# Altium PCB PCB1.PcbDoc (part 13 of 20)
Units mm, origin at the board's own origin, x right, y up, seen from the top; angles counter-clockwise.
Board outline 294.51 x 138.18 mm, 12 copper layers (Top Layer 1 _Signal, L2_GND, L3_Signals, L4_GND, L5_POWER, L6_Signals, L7_GND, L8_Signals, L9_GND, L10_POWER, L11_GND, Bottom Layer_Signals), stack 1.788 mm thick; 1254 components, 836 nets, 5699 pads, 2073 vias.
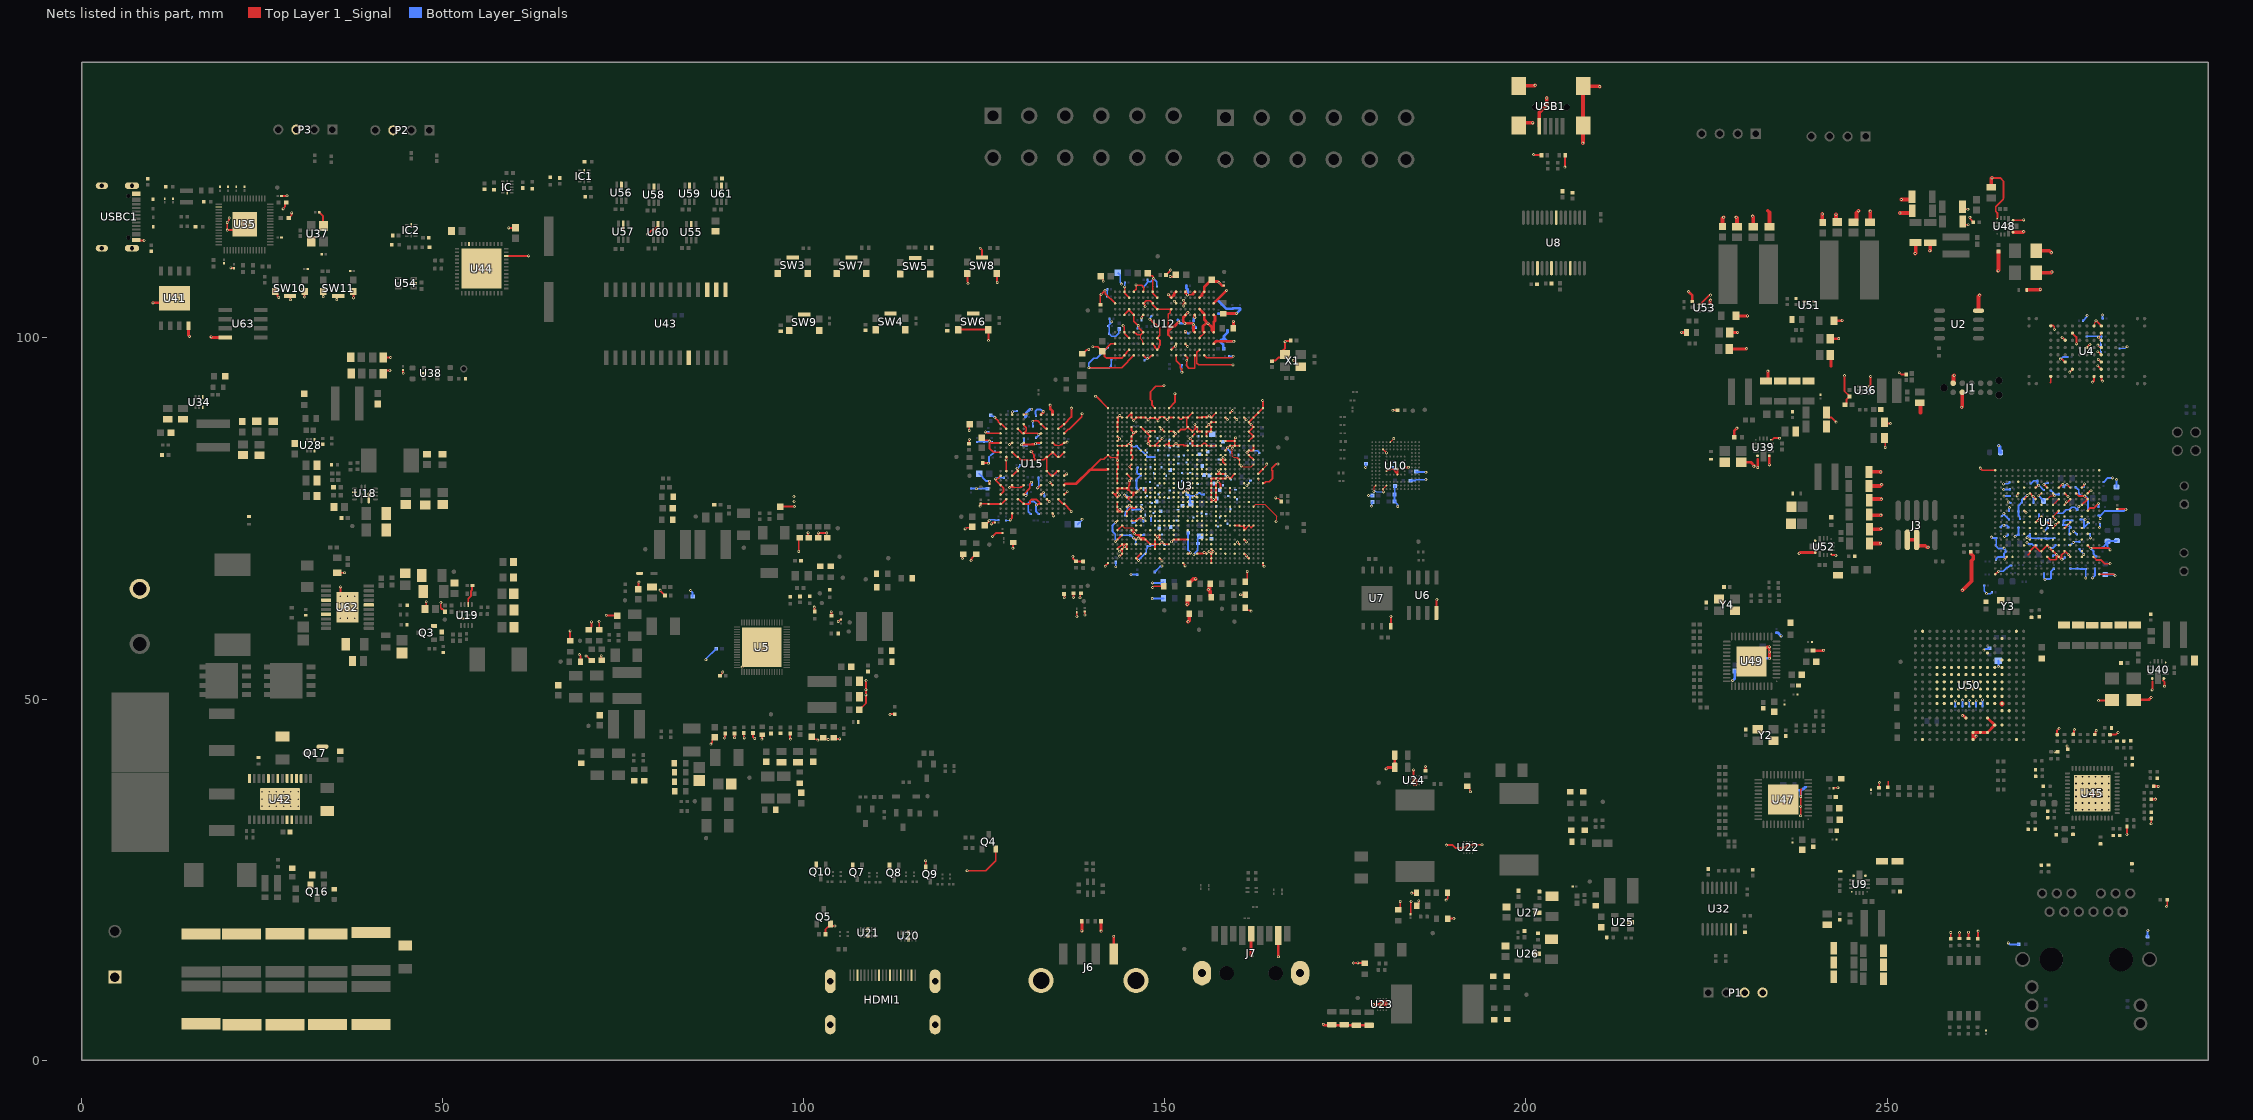
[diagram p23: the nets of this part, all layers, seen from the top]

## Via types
v1: diameter 0.4, hole 0.2, Top Layer 1 _Signal to Bottom Layer_Signals, 2009 vias
v2: diameter 0.508, hole 0.254, Top Layer 1 _Signal to Bottom Layer_Signals, 36 vias
v3: diameter 0.5, hole 0.2, Top Layer 1 _Signal to Bottom Layer_Signals, 12 vias
v4: diameter 1.27, hole 0.711, Top Layer 1 _Signal to Bottom Layer_Signals, 6 vias
v5: diameter 0.3, hole 0.2, Top Layer 1 _Signal to Bottom Layer_Signals, 5 vias
v6: diameter 0.254, hole 0.2, Top Layer 1 _Signal to Bottom Layer_Signals, 3 vias
v7: diameter 0.305, hole 0.2, Top Layer 1 _Signal to Bottom Layer_Signals, 1 vias
v8: diameter 0.254, hole 0.152, Top Layer 1 _Signal to Bottom Layer_Signals, 1 vias

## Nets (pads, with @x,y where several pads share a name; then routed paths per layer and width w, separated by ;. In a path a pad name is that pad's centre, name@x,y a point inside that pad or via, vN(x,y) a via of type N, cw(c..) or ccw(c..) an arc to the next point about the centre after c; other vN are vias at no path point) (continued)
GND: (continued)
  Top Layer 1 _Signal w0.254: USBC1.B1_A12@7.558,113.555 7.6,113.513 v1(8.645,113.513) ; v1(20.44,116.607) 20.413,116.579 20.413,116.289 20.161,116.038 v1(20.161,115.998) 20.161,115.51 20.168,115.504 v1(20.168,114.923) 21.764,114.923 U35.61@22.569,115.727 ; v1(20.675,109.706) 20.692,109.69 21.105,109.69 21.109,109.685 C565.1@21.109,109.673 ; SW10.2@26.807,106.414 27.13,106.091 27.13,105.796 27.301,105.624 27.301,105.619 v1(27.304,105.616) ; C574.1@27.682,119.646 28.404,119.646 v1(28.444,119.686) ; v1(27.903,117.875) 27.903,117.915 28.185,118.197 28.185,118.634 28.308,118.757 C453.1@28.358,118.757 ; C451.1@28.692,116.61 28.742,116.61 28.865,116.733 28.865,116.783 29.068,116.986 29.068,117.279 v1(29.096,117.307) ; SW10.5@28.857,105.789 28.902,105.744 v1(28.902,105.285) ; v1(30.886,105.668) 30.886,106.393 SW10.1@30.907,106.414 ; C560.2@32.89,117.388 32.91,117.388 33.408,116.891 33.408,115.615 U37.2@33.497,115.526 ; v1(33.458,105.711) 33.458,106.385 SW11.2@33.493,106.419 ; v1(35.335,105.297) 35.335,105.646 35.483,105.794 SW11.5@35.543,105.794 ; R302.1@35.411,67.487 35.415,67.482 v1(36.42,67.482) ; v3(35.818,64.211) 35.859,64.253 v1(35.859,65.517) ; SW11.1@37.593,106.419 37.652,106.36 v1(37.652,105.543) ; C483.2@41.776,95.03 41.776,95.109 42.176,95.51 v1(42.679,95.51) ; C484.2@41.776,97.293 v1(42.783,97.293) v1@42.825,97.335 ; C194.1@44.492,95.549 44.492,95.161 v1(44.541,95.113) ; C198.1@47.565,62.464 47.728,62.626 v1(47.728,63.461) ; v1(49.746,63.343) 49.731,63.329 49.731,62.607 49.897,62.442 49.976,62.442 50.29,62.128 R86.1@50.29,62.103 ; U19.10@53.538,63.083 53.538,63.889 53.937,64.288 53.937,64.985 54.074,65.122 54.074,65.668 R88.1@54.133,65.728 ; U44.46@58.789,111.359 58.791,111.357 61.899,111.357 v1(61.903,111.352) ; v1(59.153,115.242) 60.04,115.242 C591.2@60.074,115.276 ; v1(67.638,59.431) C181.2@67.639,58.084 C181.2@67.639,58.084 ; v1(68.924,56.152) 68.924,56.112 69.089,55.947 C180.2@69.089,55.175 ; v1(69.843,55.96) 69.965,55.96 70.588,55.337 C66.2@70.663,55.337 ; C65.2@70.255,59.598 70.33,59.598 70.578,59.846 70.578,59.921 70.609,59.952 v1(70.609,60.675) ; v1(71.655,60.707) 71.676,60.686 C61.2@71.676,59.614 ; v1(71.953,55.992) 71.953,55.433 C67.2@72.025,55.361 ; v1(72.654,61.603) 72.693,61.603 72.745,61.55 C442.2@74.177,61.55 ; C59.2@77.102,65.213 77.102,66.071 77.187,66.155 v1(77.187,66.195) ; v1(80.1,65.077) 80.1,65.019 C314.1@80.773,64.346 ; v1(87.138,43.767) 87.138,43.807 87.317,43.986 87.317,44.382 C444.2@87.64,44.705 ; C558.1@88.386,53.208 88.716,53.537 88.716,53.683 v1(88.775,53.741) ; v1(89.045,44.601) 89.073,44.629 89.073,45.162 C557.1@89.126,45.216 ; C556.1@90.412,45.232 90.413,45.232 v1(90.414,44.634) v1(90.414,44.634) ; v1(91.458,54.429) U5.69@94.199,57.17 ; C553.2@91.693,45.282 91.693,44.691 v1(91.758,44.626) ; C555.1@92.963,45.284 92.963,44.758 93.18,44.541 v1(93.215,44.541) ; v1(94.193,44.457) 94.21,44.474 94.21,45.025 R20.1@94.227,45.042 ; C446.2@96.775,76.616 96.806,76.647 v1(98.704,76.647) ; R37.1@98.108,45.21 98.108,44.559 98.177,44.489 v1(98.177,44.45) ; v1(99.304,70.432) 99.304,72.198 C164.2@99.431,72.324 ; v1(100.594,73.03) 100.594,72.415 C165.2@100.706,72.304 ; C72.2@101.112,44.752 101.435,44.429 101.794,44.429 101.914,44.309 v1(101.953,44.309) ; v1(101.451,62.723) 101.478,62.696 101.478,62.142 C171.2@101.505,62.115 ; C166.2@101.976,72.304 102.017,72.345 v1(102.017,72.993) 102.021,72.989 103.185,72.989 v1(103.189,72.985) ; C71.2@102.725,44.648 102.949,44.423 103.361,44.423 v1(103.389,44.395) ; R105.1@102.999,17.418 102.999,18.085 103.383,18.47 103.504,18.47 103.702,18.668 Q5.2@103.702,18.764 ; Q5.2@103.702,18.843 Q5.2@103.702,18.764 ; v1(103.802,62.089) 103.821,62.071 103.821,61.522 C172.2@103.84,61.504 ; C70.2@104.121,44.638 104.288,44.471 v1(104.987,44.471) ; v1(104.319,18.566) 103.9,18.566 Q5.2@103.702,18.764 ; v1(104.768,60.747) 104.808,60.747 105.047,60.986 105.153,60.986 C176.1@105.166,60.999 ; C49.2@107.701,48.494 108.614,49.407 108.614,50.553 v1(108.602,50.566) v1(108.602,51.291) 108.602,51.906 108.627,51.932 v1(108.627,52.548) ; v1(111.941,47.855) 111.981,47.855 112.034,47.908 C467.2@112.586,47.908 ; v1(116.864,27.606) 116.864,27.563 116.884,27.544 Q9.2@116.884,26.607 ; SW6.3@121.419,101.145 SW6.4@125.519,101.145 125.58,101.084 v1(125.58,99.636) ; v1(121.963,69.435) 121.963,69.971 C235.2@122.062,70.07 ; v1(122.344,73.554) 122.383,73.554 122.554,73.724 123.217,73.724 C431.2@123.357,73.864 ; v1(122.614,26.214) 125.21,26.214 126.574,27.577 Q4.2@126.574,29.214 ; SW8.3@122.643,108.916 122.694,108.865 122.694,107.783 122.713,107.764 122.713,107.542 v1(122.741,107.514) ; v1(123.181,69.166) 123.209,69.194 123.209,69.419 123.832,70.042 C234.2@123.907,70.042 ; v1(124.423,76.701) 124.423,76.74 124.478,76.795 124.478,77.051 124.491,77.064 C417.2@124.501,77.064 124.511,77.064 124.54,77.035 C420.2@125.571,77.035 125.581,77.035 125.615,77 126.877,77 126.879,77.002 127.232,77.002 U15.C12@127.25,77.021 127.268,77.039 127.418,77.039 U15.D11@128.05,77.671 ; v1(124.435,112.422) 124.693,112.164 SW8.5@124.693,111.141 ; C414.2@124.646,86.165 124.609,86.129 124.9,85.838 125.54,85.838 125.672,85.706 v1(125.711,85.706) ; C415.2@124.772,82.679 124.791,82.66 125.538,82.66 v1(125.557,82.641) ; C432.2@125.089,74.043 125.657,74.611 v1(125.657,74.692) ; C395.2@125.724,79.78 125.727,79.783 125.727,80.148 v1(125.73,80.151) ; v1(125.97,74.251) 126.01,74.251 126.2,74.441 126.433,74.441 126.446,74.454 C410.2@126.446,74.464 ; v1(126.154,72.525) 126.154,72.531 126.623,73 C401.2@127.508,73 ; SW8.4@126.743,108.916 126.743,107.73 v1(126.783,107.69) ; U15.E12@127.25,78.321 127.25,78.335 127.636,78.721 127.636,79.261 127.276,79.621 U15.G12@127.25,79.621 126.602,80.269 126.602,80.446 v1(126.574,80.474) 126.602,80.502 126.831,80.502 U15.J12@127.25,80.921 ; U15.P12@127.25,84.171 126.322,84.171 126.107,84.386 126.01,84.386 125.722,84.674 125.722,85.695 v1(125.711,85.706) ; U15.T12@127.25,85.471 125.986,85.471 125.751,85.706 v1(125.711,85.706) ; U15.K11@128.05,81.571 128.035,81.586 128.035,83.094 v1(128.02,83.109) 128.041,83.13 128.041,83.206 128.06,83.225 128.06,83.51 U15.N11@128.05,83.521 ; v1(128.488,85.246) 128.6,85.246 128.824,85.471 U15.T10@128.85,85.471 ; v1(128.491,79.281) v1@128.501,79.281 ; v1(128.592,74.811) 128.85,75.069 U15.A10@128.85,75.721 ; U15.G10@128.85,79.621 128.84,79.621 v1@128.501,79.281 ; U15.J10@128.85,80.921 129.482,81.552 129.632,81.552 U15.K9@129.65,81.571 129.632,81.589 129.632,81.833 v1(129.535,81.93) ; U15.P10@128.85,84.171 129.482,83.539 129.632,83.539 U15.N9@129.65,83.521 129.665,83.521 130.05,83.135 132.151,83.135 ; v1(128.963,70.876) 128.963,71.647 C412.2@128.994,71.678 ; 129.091,79.3 129.019,79.372 128.622,79.372 128.531,79.281 v1@128.501,79.281 ; U15.D9@129.65,77.671 129.668,77.652 129.792,77.652 130.424,77.021 U15.C8@130.45,77.021 130.468,77.002 130.536,77.002 130.554,76.985 131.19,76.985 131.339,77.134 131.339,77.465 131.488,77.614 132.257,77.614 U15.C5@132.85,77.021 132.832,77.002 132.401,77.002 132.268,76.869 v1(132.228,76.869) ; 129.947,79.304 129.966,79.304 130.003,79.341 130.144,79.341 130.424,79.621 U15.G8@130.45,79.621 ; U15.T8@130.45,85.471 130.45,85.445 v1@130.227,85.222 ; v1(130.752,78.181) 130.724,78.209 130.588,78.209 130.476,78.321 U15.E8@130.45,78.321 131.301,79.171 131.301,79.762 131.522,79.984 v1(131.522,80.023) ; 131.577,85.354 132.085,85.354 v1(132.09,85.35) ; v1@131.653,84.273 131.517,84.273 v1(131.489,84.245) 131.489,84.206 131.876,83.819 131.876,83.409 132.151,83.135 ; v1(131.711,88.466) 131.75,88.466 131.82,88.536 132.384,88.536 U15.Y5@132.85,88.071 132.876,88.071 133.508,87.439 133.632,87.439 U15.W4@133.65,87.421 ; v1(132.381,79.242) 132.446,79.242 132.824,79.621 U15.G5@132.85,79.621 132.842,79.629 U15.G5@132.842,79.651 ; v1(132.546,86.667) 132.586,86.667 132.659,86.74 132.671,86.74 132.683,86.752 132.832,86.752 U15.V5@132.85,86.771 ; U15.E5@132.85,78.321 132.876,78.321 v1(133.17,78.615) ; U15.T5@132.85,85.471 132.25,85.471 132.129,85.35 v1(132.09,85.35) ; U15.D4@133.65,77.671 133.976,77.344 v1(133.991,77.344) ; v1(134.083,79.995) 134.153,79.925 134.153,79.918 U15.G3@134.45,79.621 ; U15.A3@134.45,75.721 134.468,75.702 134.468,75.554 134.544,75.478 134.544,75.381 v1(134.572,75.353) ; U15.T3@134.45,85.471 134.476,85.471 134.8,85.146 135.029,85.146 ; U15.D2@135.25,77.671 135.882,77.039 136.032,77.039 U15.C1@136.05,77.021 136.542,76.528 136.542,76.461 v1(137.03,75.973) ; U15.K2@135.25,81.571 135.232,81.552 135.082,81.552 U15.J3@134.45,80.921 134.432,80.939 134.282,80.939 U15.K4@133.65,81.571 U15.N4@133.65,83.521 ; U15.W2@135.25,87.421 135.276,87.421 135.548,87.693 135.646,87.693 136.024,88.071 U15.Y1@136.05,88.071 137.049,89.07 v1(137.049,90.275) ; C311.2@136.036,64.541 136.086,64.491 136.086,64.033 v1(136.07,64.018) ; U15.E1@136.05,78.321 136.076,78.321 136.453,78.698 v1(136.482,78.698) ; U15.J1@136.05,80.921 136.076,80.921 136.333,81.178 v1(136.413,81.178) ; U15.P1@136.05,84.171 135.418,83.539 135.268,83.539 U15.N2@135.25,83.521 135.232,83.539 135.082,83.539 U15.P3@134.45,84.171 133.818,83.539 133.668,83.539 U15.N4@133.65,83.521 ; U15.V1@136.05,86.771 136.634,87.355 136.738,87.355 138.489,89.106 138.489,89.457 v1(138.538,89.506) ; v1(137.26,69.729) 137.26,69.484 137.675,69.069 C283.1@137.7,69.069 137.711,69.058 138.666,69.058 C289.1@138.677,69.047 ; v1(137.323,64.065) 137.34,64.082 137.34,64.652 C304.1@137.356,64.669 ; v1(138.249,64.018) 138.277,64.045 138.277,64.568 C309.1@138.366,64.657 ; C305.1@138.908,62.103 138.916,62.095 138.916,61.644 v1(138.924,61.636) ; 139.492,81.597 139.653,81.758 141.105,83.209 141.561,83.209 U3.L1@142.129,83.778 ; v1(140.401,91.928) 140.48,91.928 U3.A1@142.129,90.278 ; C340.2@141.306,98.16 141.629,97.837 141.629,97.491 141.917,97.203 144.004,97.203 144.39,97.589 U12.C1@144.404,97.589 144.404,97.615 144.677,97.887 144.677,97.985 145.054,98.363 U12.D2@145.054,98.389 ; U3.L1@142.111,83.778 U3.L1@142.129,83.778 ; 142.58,83.453 142.472,83.453 142.147,83.778 U3.L1@142.129,83.778 ; U3.W2@142.779,78.578 142.797,78.578 143.035,78.34 143.209,78.34 ; v1(143.14,71.82) 143.14,71.823 143.221,71.904 143.237,71.904 143.411,72.078 U3.AJ3@143.429,72.078 U3.AH4@144.079,72.728 ; v1(143.152,74.424) 143.164,74.424 143.418,74.678 U3.AE3@143.429,74.678 ; U3.AG3@143.429,73.378 U3.AF4@144.079,74.028 ; U3.AA3@143.429,77.278 143.417,77.265 143.417,77.196 143.409,77.188 143.409,76.016 143.429,75.996 U3.AC3@143.429,75.978 U3.AC3@143.446,75.978 ; U3.Y3@143.429,77.928 U3.Y3@143.429,77.946 ; U3.U3@143.429,79.878 143.417,79.891 143.417,80.116 143.404,80.129 143.404,81.134 143.429,81.16 U3.R3@143.429,81.178 143.429,81.196 143.329,81.297 143.329,81.709 143.429,81.81 U3.P3@143.429,81.828 143.429,81.846 143.502,81.919 143.502,82.387 143.429,82.46 U3.N3@143.429,82.478 143.436,82.485 v1(143.436,83.048) 143.429,83.055 143.429,83.122 U3.M3@143.429,83.128 ; U3.K3@143.429,84.428 143.429,84.41 143.534,84.305 143.534,83.9 143.429,83.796 U3.L3@143.429,83.778 U3.M3@143.429,83.128 ; U3.J3@143.429,85.078 U3.J4@144.079,85.078 U3.J5@144.729,85.078 144.729,85.096 144.985,85.351 145.156,85.351 v1(145.184,85.379) ; U3.H3@143.429,85.728 143.429,85.746 U3.H3@143.526,85.843 ; U3.G3@143.429,86.378 143.429,86.36 143.721,86.068 v1(143.721,86.04) ; U3.F3@143.429,87.028 143.429,87.046 143.472,87.088 143.472,87.618 143.429,87.66 U3.E3@143.429,87.678 U3.D3@143.429,88.328 143.429,88.346 143.515,88.432 143.515,88.874 143.429,88.96 U3.C3@143.429,88.978 143.447,88.978 143.728,89.259 v1(143.757,89.259) 143.781,89.259 144.061,88.978 U3.C4@144.079,88.978 ; U3.M3@143.436,83.115 143.436,83.121 U3.M3@143.429,83.128 ; U3.H3@143.535,85.834 v1@143.721,86.02 ; v1(143.694,78.274) 143.694,78.21 U3.Y3@143.429,77.946 ; v1(143.763,76.278) 143.746,76.278 U3.AC3@143.446,75.978 ; U3.AC4@144.079,75.978 U3.AC3@143.446,75.978 ; v1(144.398,78.237) 144.42,78.215 144.425,78.215 144.711,77.928 U3.Y5@144.729,77.928 ; U3.AD5@144.729,75.328 U3.AC5@144.729,75.978 144.747,75.978 144.981,76.212 145.066,76.212 145.066,76.296 145.379,76.61 U3.AB6@145.379,76.628 145.397,76.628 145.579,76.446 145.83,76.446 146.011,76.628 U3.AB7@146.029,76.628 ; U3.V5@144.729,79.228 144.711,79.228 U3.V5@144.654,79.17 ; U3.R5@144.729,81.178 U3.T6@145.379,80.528 145.361,80.528 145.092,80.259 v1(145.092,80.22) 145.1,80.212 145.1,79.644 145.009,79.553 145.009,79.074 ; U3.C5@144.729,88.978 U3.B6@145.379,89.628 U3.C6@145.379,88.978 145.379,88.96 145.634,88.706 145.634,88.604 v1(145.662,88.576) 145.662,88.593 146.029,88.961 U3.C7@146.029,88.978 U3.C8@146.679,88.978 U3.C9@147.329,88.978 147.347,88.978 147.666,88.659 v1(147.684,88.659) 147.734,88.709 147.734,88.714 147.979,88.96 U3.C10@147.979,88.978 147.997,88.978 148.047,88.928 148.562,88.928 148.611,88.978 U3.C11@148.629,88.978 148.629,88.96 148.66,88.93 148.66,88.917 v1(149.065,88.511) 149.093,88.539 149.093,88.774 149.279,88.96 U3.C12@149.279,88.978 149.297,88.978 149.395,89.076 149.814,89.076 149.911,88.978 U3.C13@149.929,88.978 149.947,88.978 150.198,88.727 v1(150.385,88.727) 150.405,88.747 150.405,88.786 150.579,88.96 U3.C14@150.579,88.978 U3.C15@151.229,88.978 ; U3.AG6@145.379,73.378 145.392,73.365 145.392,73.296 v1(145.789,72.899) 145.829,72.899 145.999,72.728 U3.AH8@146.679,72.728 146.367,72.416 146.367,72.309 v1(146.339,72.281) 147.109,72.281 U3.AJ9@147.311,72.078 ; U3.AA6@145.379,77.278 U3.Y5@144.729,77.928 ; U3.P6@145.379,81.828 145.379,81.846 145.121,82.104 v6(145.121,82.211) 145.379,82.469 U3.N6@145.379,82.478 ; U3.M6@145.379,83.128 145.379,83.146 145.509,83.275 145.509,83.63 145.379,83.76 U3.L6@145.379,83.778 145.379,83.796 145.294,83.881 145.294,84.325 145.379,84.41 U3.K6@145.379,84.428 U3.J6@145.379,85.078 145.379,85.096 145.329,85.147 145.329,85.659 145.379,85.71 U3.H6@145.379,85.728 U3.G6@145.379,86.378 145.379,86.396 145.635,86.651 145.635,86.843 v1(145.663,86.871) ; U3.E6@145.379,87.678 145.392,87.665 145.392,87.182 145.663,86.911 v1(145.663,86.871) ; v1(145.681,72.312) 145.729,72.264 145.826,72.264 146.011,72.078 U3.AJ7@146.029,72.078 ; 145.682,78.268 145.682,78.258 ; U3.F7@146.029,87.028 146.029,87.024 145.905,86.899 145.691,86.899 v1(145.663,86.871) ; v1(146.349,69.182) 146.337,69.182 146.041,69.478 U3.AN7@146.029,69.478 U3.AM8@146.679,70.128 ; U3.AJ8@146.679,72.078 U3.AJ9@147.311,72.078 ; U3.AB8@146.679,76.628 146.679,76.61 146.865,76.424 146.865,76.322 v1(146.893,76.294) ; U3.V8@146.679,79.228 146.679,79.21 146.649,79.18 146.649,79.157 v1(146.3,78.808) 146.259,78.808 U3.W7@146.029,78.578 U3.W6@145.379,78.578 ; U3.E8@146.679,87.678 U3.F9@147.329,87.028 U3.G10@147.979,86.378 147.979,86.36 147.7,86.081 v1@147.7,85.431 ; U3.W9@147.329,78.578 U3.V9@147.329,79.228 ; v1(147.721,87.048) 147.726,87.053 147.936,87.053 147.961,87.028 U3.F10@147.979,87.028 147.997,87.028 148.106,87.137 148.503,87.137 148.611,87.028 U3.F11@148.629,87.028 ; U3.H10@147.979,85.728 147.979,85.71 v1@147.7,85.431 ; U12.J3@148.304,99.189 148.304,99.163 148.622,98.846 148.622,98.722 U12.K2@148.954,98.389 148.954,98.415 149.176,98.636 149.176,98.865 149.34,99.029 149.34,99.588 148.954,99.974 U12.K4@148.954,99.989 ; v1(148.313,65.443) 148.353,65.443 148.532,65.622 C18.2@149.827,65.622 ; U3.AL11@148.629,70.778 U3.AK11@148.629,71.428 ; U3.AJ11@148.629,72.078 U3.AK11@148.629,71.428 ; U3.AH11@148.629,72.728 148.647,72.728 148.888,72.487 148.968,72.487 v1(148.996,72.459) 149.003,72.459 149.272,72.728 U3.AH12@149.279,72.728 U3.AJ12@149.279,72.078 ; U3.A11@148.629,90.278 148.227,90.681 148.227,91.218 148.008,91.437 148.008,92.558 148.761,93.312 149.733,93.312 149.839,93.418 v1(149.879,93.418) ; U3.AN12@149.279,69.478 149.279,69.467 149.604,69.142 v1(149.604,69.13) ; U3.J12@149.279,85.078 U3.J11@148.629,85.078 ; v1(149.622,86.051) 149.297,85.728 U3.H12@149.279,85.728 U3.J11@148.629,85.078 ; U3.J13@149.929,85.078 149.947,85.078 150.158,85.289 150.35,85.289 150.561,85.078 U3.J14@150.579,85.078 ; 150.455,100.438 U12.N4@150.904,99.989 ; U3.AK14@150.579,71.428 U3.AK13@149.929,71.428 149.911,71.428 149.623,71.716 v1(149.577,71.716) 149.572,71.716 149.284,71.428 U3.AK12@149.279,71.428 U3.AK11@148.629,71.428 ; U3.H14@150.579,85.728 U3.J14@150.579,85.078 ; U3.A14@150.579,90.278 151.398,91.097 v1(151.398,92.275) ; v1(150.92,71.771) 150.929,71.781 150.932,71.781 U3.AJ15@151.229,72.078 U3.AJ16@151.879,72.078 U3.AJ18@153.179,72.078 ; U3.G15@151.229,86.378 151.229,86.396 151.464,86.631 151.464,86.726 v1(151.492,86.754) ; v1@151.542,85.411 151.546,85.411 U3.J16@151.879,85.078 151.897,85.078 152.022,85.202 152.529,85.202 152.641,85.091 153.167,85.091 U3.J18@153.179,85.078 ; v1(151.541,85.412) 151.541,85.401 151.229,85.089 U3.J15@151.229,85.078 U3.J14@150.579,85.078 ; U3.F16@151.879,87.028 151.897,87.028 152.175,87.306 152.79,87.306 U3.E18@153.179,87.696 ; U3.C16@151.879,88.978 151.897,88.978 152.132,88.743 152.277,88.743 152.511,88.978 U3.C17@152.529,88.978 U3.C18@153.179,88.978 ; U3.W17@152.529,78.578 152.547,78.578 152.78,78.811 152.854,78.811 v1(152.882,78.839) ; U3.AM18@153.179,70.128 153.192,70.141 153.429,70.141 153.53,70.242 v1(153.57,70.242) ; U3.V18@153.179,79.228 153.179,79.21 153.433,78.956 153.433,78.92 ; v1(153.502,86.06) 153.502,86.058 153.829,85.73 U3.H19@153.829,85.728 U3.J19@153.829,85.078 U3.J20@154.479,85.078 U3.J21@155.129,85.078 155.142,85.091 155.142,85.173 155.382,85.413 155.592,85.413 155.767,85.239 155.767,85.091 U3.J22@155.779,85.078 U3.J23@156.429,85.078 U3.J24@157.079,85.078 ; U3.F19@153.811,87.028 153.778,87.061 153.179,87.66 U3.E18@153.179,87.678 U3.E18@153.179,87.696 ; U3.G19@153.829,86.378 153.829,86.396 154.097,86.663 154.097,86.669 154.146,86.719 ; U3.F19@153.829,87.028 153.829,87.046 154.2,87.417 154.2,87.935 154.152,87.983 v1(154.152,88.023) ; U3.B19@153.829,89.628 U3.C18@153.179,88.978 ; v1(154.247,78.134) 154.26,78.134 154.466,77.928 U3.Y20@154.479,77.928 ; U3.AM20@154.479,70.128 155.239,70.128 155.398,70.287 v1(155.437,70.287) 155.603,70.287 155.761,70.128 U3.AM22@155.779,70.128 ; U3.E20@154.479,87.678 U3.F20@154.479,87.028 U3.F21@155.129,87.028 ; U3.C20@154.479,88.978 U3.C21@155.129,88.978 155.142,88.991 155.235,88.991 155.273,89.028 155.711,89.028 155.761,88.978 U3.C22@155.779,88.978 155.797,88.978 155.989,89.17 156.12,89.17 v1(156.148,89.198) 156.21,89.198 U3.C23@156.429,88.978 U3.B24@157.079,89.628 ; U12.W4@154.804,99.989 154.804,100.015 154.852,100.063 154.852,100.098 155.436,100.681 155.436,100.771 U12.Y5@155.454,100.789 ; U3.G22@155.779,86.378 U3.F22@155.779,87.028 U3.F23@156.429,87.028 156.417,87.041 156.417,87.132 156.368,87.181 156.368,87.599 156.429,87.66 U3.E23@156.429,87.678 156.429,87.696 156.127,87.998 v1@156.088,87.998 ; U3.E22@155.779,87.678 155.779,87.69 156.076,87.986 v1(156.076,87.998) v1@156.088,87.998 ; v1(156.123,70.441) 156.123,70.438 156.429,70.131 U3.AM23@156.429,70.128 ; U3.AL23@156.429,70.778 156.429,70.76 156.659,70.531 156.659,70.447 v1(156.687,70.419) ; U3.AA23@156.429,77.278 U3.AA23@156.429,77.296 ; U3.D23@156.474,88.409 156.429,88.364 U3.D23@156.429,88.328 ; U3.U24@157.079,79.878 U3.V24@157.079,79.228 U3.W24@157.079,78.578 U3.Y24@157.079,77.928 U3.AA24@157.079,77.278 157.077,77.278 156.73,77.625 v1(156.728,77.625) 156.63,77.527 156.63,77.496 U3.AA23@156.429,77.296 ; U3.R24@157.079,81.178 U3.R25@157.729,81.178 ; U3.D24@157.079,88.328 157.072,88.321 156.436,88.321 U3.D23@156.429,88.328 ; v1(157.377,80.115) 157.377,80.076 157.717,79.737 157.717,79.241 U3.V25@157.729,79.228 ; v1(157.454,81.59) 157.454,81.538 157.479,81.513 157.479,81.446 157.729,81.196 U3.R25@157.729,81.178 ; v1(158.068,83.422) 158.04,83.394 158.04,83.062 158.023,83.045 158.023,82.834 U3.N26@158.379,82.478 ; U3.R26@158.379,81.178 U3.R25@157.729,81.178 ; U3.K26@158.379,84.428 158.379,84.446 158.698,84.764 v1(158.698,84.801) 158.734,84.801 159.011,85.078 U3.J27@159.029,85.078 U3.J28@159.679,85.078 ; U3.H26@158.379,85.728 U3.H28@159.679,85.728 ; U3.C26@158.379,88.978 v1(158.66,88.698) ; U3.B27@159.029,89.628 159.047,89.628 159.372,89.953 v1(159.377,89.953) ; U3.T27@159.042,80.515 U3.T27@159.029,80.528 ; U3.AF28@159.679,74.028 U3.AF29@160.329,74.028 160.347,74.028 160.45,73.925 160.858,73.925 160.961,74.028 U3.AF30@160.979,74.028 U3.AG30@160.979,73.378 U3.AF31@161.629,74.028 161.647,74.028 161.925,73.75 161.984,73.75 162.261,74.028 U3.AF32@162.279,74.028 ; U3.R28@159.679,81.178 U3.T27@159.029,80.528 ; U3.C28@159.679,88.978 159.697,88.978 159.958,88.717 v1(159.958,88.699) ; v1(159.788,86.175) 159.679,86.067 U3.H28@159.679,85.728 ; 160.04,83.399 160.311,83.128 U3.M29@160.329,83.128 ; v1(160.055,71.716) 160.055,71.709 160.329,71.435 U3.AK29@160.329,71.428 ; U3.J29@160.329,85.078 U3.J28@159.679,85.078 ; U3.AM30@160.979,70.128 v1(161.291,69.817) U3.AN31@161.629,69.478 ; U3.AJ30@160.979,72.078 160.979,72.06 161.26,71.78 161.26,71.775 v1(161.285,71.75) ; U3.C30@160.979,88.978 160.979,88.96 161.244,88.695 161.244,88.687 v1(161.254,88.676) ; v1(161.372,84.113) 161.412,84.113 161.726,84.428 U3.K32@162.279,84.428 U3.J32@162.279,85.078 ; U3.L31@161.629,83.778 U3.M32@162.279,83.128 ; U3.H31@161.629,85.728 U3.G32@162.279,86.378 162.279,86.384 162.162,86.502 162.155,86.502 U3.F31@161.629,87.028 U3.E32@162.279,87.678 162.268,87.678 161.951,87.995 v1(161.94,87.995) 161.94,88.006 161.629,88.317 U3.D31@161.629,88.328 U3.A34@163.579,90.278 163.567,90.291 163.567,91.308 v1(163.541,91.334) ; U3.R33@162.929,81.178 U3.P34@163.579,81.828 ; U3.AP34@163.579,68.828 163.592,68.815 163.592,68.575 163.75,68.418 v1(163.75,68.378) ; U3.U34@163.579,79.878 163.592,79.891 163.756,79.891 163.807,79.941 163.822,79.941 163.968,80.087 164.427,80.087 164.91,80.57 164.91,81.578 164.824,81.664 ; C31.1@164.827,96.771 164.909,96.853 165.296,96.853 165.723,97.281 166.19,97.281 X1.2@166.622,97.713 ; X1.2@166.146,98.089 166.641,98.585 v1(166.641,99.476) 166.681,99.476 166.777,99.573 167.344,99.573 C33.2@167.418,99.647 ; v1(167.786,96.913) 167.822,96.913 168.722,96.013 X1.4@168.822,96.013 ; v1(176.127,13.444) 176.133,13.45 176.728,13.45 v1(176.734,13.457) 176.744,13.447 177.663,13.447 C506.2@177.672,13.438 ; U10.C4@180.204,84.57 180.691,84.082 v1(180.691,84.078) ; U10.J5@180.704,81.57 180.88,81.747 181.193,81.747 181.264,81.818 181.605,81.818 182.204,81.219 ; U7.4@181.28,60.067 181.291,60.078 181.291,61.438 v1(181.303,61.45) ; v1(181.585,89.989) 181.599,89.975 182.202,89.975 C212.2@182.216,89.96 ; U10.K8@182.204,81.07 182.204,81.219 ; v1(182.213,81.865) 182.204,81.856 182.204,81.219 ; U10.H10@183.204,82.07 183.697,82.07 v1(183.713,82.085) ; v1(184.437,40.182) 184.447,40.172 U24.C1@184.447,39.357 U24.C2@184.447,38.957 U24.C3@184.447,38.557 U24.C4@184.447,38.157 U24.B4@184.847,38.157 U24.B3@184.847,38.557 U24.B2@184.847,38.957 ; v1(186.065,40.682) 186.073,40.674 186.073,40.088 R123.1@186.081,40.08 ; U6.4@187.605,61.922 187.605,63.649 187.67,63.714 v1(187.67,63.753) ; v1(188.979,29.778) 189.868,29.778 190.289,29.358 191.08,29.358 191.184,29.461 U22.C1@191.399,29.461 U22.C2@191.799,29.461 U22.B2@191.799,29.861 U22.B3@192.198,29.861 U22.C3@192.198,29.461 ; C512.2@189.165,19.598 189.171,19.603 v1(190.026,19.603) ; v1(201.056,125.376) 201.084,125.348 202.09,125.348 U30.2@202.156,125.282 ; v1(205.401,123.656) 205.421,123.676 U31.2@205.421,125.282 ; U53.4@224.016,104.67 224.137,104.67 225.39,105.922 v1(225.557,105.922) ; 234.142,85.936 234.37,86.164 234.58,86.164 234.607,86.137 235.106,86.137 v1(235.134,86.109) ; C353.1@241.595,89.684 241.595,89.309 241.943,88.961 242.317,88.961 v1(242.943,88.335) ; U52.1@242.266,70.05 242.391,69.924 242.883,69.924 v1(242.911,69.896) ; v1(244.112,94.787) 244.112,92.611 R142.1@244.822,91.902 ; R143.1@244.2,90.739 244.366,90.904 244.366,91.445 R142.1@244.822,91.902 ; R142.1@244.824,91.902 R142.1@244.822,91.902 ; v1(247.721,94.662) 247.721,93.271 U36.3@247.739,93.253 ; C348.2@249.655,86.159 249.753,86.061 v1(249.753,84.835) ; C354.2@249.657,88.331 249.843,88.145 v1(250.49,88.145) ; v1(251.689,95.179) 251.729,95.179 251.969,94.939 C487.1@252.675,94.939 ; v1(258.816,17.667) 258.818,17.665 R19.1@258.82,16.799 R19.1@258.82,16.799 ; v1(260.036,17.66) 260.043,17.653 R18.1@260.043,16.834 ; C532.1@260.447,118.172 260.447,118.159 260.795,117.811 v1(261.198,117.811) ; C531.1@260.48,116.119 260.48,116.022 260.828,115.674 v1(261.243,115.674) ; 261.281,17.086 v1(261.283,17.71) v1(261.283,17.71) ; v1(261.465,116.709) 261.493,116.681 261.493,116.503 R162.1@261.96,116.034 R162.1@261.96,116.034 ; R16.1@262.573,16.81 262.592,16.83 262.592,17.835 v1(262.612,17.854) v1@262.572,17.854 ; v1(262.905,81.972) 263.196,81.68 U1.W1@264.981,81.68 ; v1(264.534,122.167) 265.648,122.167 266.126,121.688 266.126,119.336 266.096,119.305 266.096,119.179 265.051,118.134 265.051,117.522 265.286,117.286 265.286,116.674 ; U1.W19@264.981,67.28 265.002,67.28 265.375,67.654 265.424,67.654 v1(265.452,67.682) ; v1(268.001,78.126) 268.029,78.154 268.029,78.308 268.181,78.459 U1.R5@268.181,78.48 ; U1.P8@268.981,76.079 v1(269.244,75.815) ; U1.P6@268.981,77.68 269.307,78.006 269.307,78.033 269.414,78.14 v1(269.414,78.18) ; U1.N5@269.781,78.48 269.802,78.48 270.198,78.083 v1(270.227,78.083) 270.227,78.054 270.581,77.701 U1.M6@270.581,77.68 ; U1.M4@270.581,79.28 270.602,79.28 270.888,79.566 270.959,79.566 v1(270.987,79.594) ; v1(271.71,79.696) 271.75,79.696 271.775,79.721 271.775,79.666 272.16,79.28 U1.K4@272.181,79.28 ; U1.K16@272.181,69.68 272.582,69.279 273.34,69.279 273.488,69.428 v1@273.488,69.987 ; 272.615,93.808 272.672,93.864 U4.P9@272.672,94.669 ; U4.P2@272.672,101.669 272.709,101.706 273.025,101.706 273.151,101.58 273.151,101.219 v1(273.179,101.191) ; U1.J15@272.981,70.48 272.995,70.48 273.474,70.002 v1(273.488,70.002) v1@273.488,69.987 ; v1(273.252,42.668) 273.623,42.668 R375.1@273.652,42.696 ; R386.1@273.558,45.081 273.558,45.637 v1(273.83,45.909) ; U1.H4@273.781,79.28 273.801,79.28 274.177,79.656 274.304,79.656 v1(274.332,79.684) ; v1(273.993,97.069) 274.021,97.041 274.247,97.041 274.618,96.669 U4.M7@274.672,96.669 ; v1(274.242,100.066) 274.258,100.066 274.655,99.669 U4.M4@274.672,99.669 ; U1.G15@274.581,70.48 274.602,70.48 U1.G15@274.653,70.428 ; U1.G5@274.581,78.48 275.019,78.042 v1(275.059,78.042) ; v1(274.864,77.297) 274.892,77.324 275.005,77.324 275.36,77.68 U1.F6@275.381,77.68 ; v1(274.922,79.688) 275.315,79.295 275.366,79.295 U1.F4@275.381,79.28 ; v1(274.93,43.491) 274.958,43.463 274.958,43.135 R396.1@275.043,43.051 ; v1(275.306,95.262) v1(275.306,95.262) 275.672,95.628 U4.L8@275.672,95.669 ; U1.F16@275.381,69.68 275.381,69.701 275.136,69.945 275.136,69.989 v1(275.108,70.017) 274.697,70.428 U1.G15@274.653,70.428 ; U4.L3@275.672,100.669 276.221,100.12 276.221,99.18 v1(276.215,99.174) ; R384.1@275.783,45.096 275.8,45.096 275.91,45.207 275.91,45.678 275.951,45.719 v1(275.951,45.758) ; U1.E5@276.16,78.459 U1.E5@276.166,78.465 ; U1.E5@276.181,78.48 U1.E5@276.166,78.465 ; U1.D7@276.981,76.88 U1.C6@277.781,77.68 277.781,77.688 277.377,78.092 v1(277.377,78.1) 276.581,78.1 276.216,78.465 U1.E5@276.166,78.465 ; U1.D4@276.981,79.28 276.981,79.301 277.295,79.615 277.295,79.756 v1(277.323,79.784) ; U4.J5@277.672,98.669 277.672,98.675 278.093,99.097 v1(278.093,99.103) ; U1.C14@277.781,71.28 277.801,71.28 278.177,70.904 280.701,70.904 280.881,70.724 v1(280.881,70.656) ; U1.C8@277.781,76.08 278.165,76.464 278.697,76.464 278.957,76.724 278.957,76.746 279.269,77.058 v1(279.269,77.098) ; U1.C5@277.781,78.48 277.784,78.48 278.144,78.839 v1(278.245,78.839) ; v1(278.477,93.884) 278.498,93.884 278.672,94.057 U4.H9@278.672,94.669 ; U1.B16@278.581,69.68 279.005,69.256 279.599,69.256 280.126,68.729 280.881,68.729 v1(280.896,68.744) ; R382.1@278.754,45.089 278.77,45.089 278.881,45.199 278.881,45.519 v1(278.976,45.614) ; v1(278.938,102.374) 278.952,102.374 279.658,101.669 U4.G2@279.672,101.669 ; v1(279.177,98.084) 279.205,98.056 279.284,98.056 U4.G6@279.672,97.669 ; v1(279.178,96.149) 279.185,96.149 279.665,95.669 U4.G8@279.672,95.669 ; v1(279.252,97.034) 279.288,96.997 279.29,96.997 279.618,96.669 U4.G7@279.672,96.669 ; v1(279.284,49.776) 281.042,49.776 C184.1@281.15,49.885 ; U1.A19@279.381,67.28 281.387,67.28 v1(281.586,67.081) ; U4.G9@279.672,94.669 279.709,94.631 279.709,94.161 279.815,94.055 v1(279.815,94.015) ; R377.1@280.867,45.066 281.662,45.066 281.961,45.366 v1(282.001,45.366) ; C183.2@281.87,76.302 281.883,76.289 283.047,76.289 v1(283.07,76.266) ; v1(283.223,31.258) 283.231,31.265 C381.2@283.231,32.347 ; v1(286.565,32.734) 286.578,32.747 286.578,33.444 R394.1@286.591,33.457 ; v1(286.711,51.254) 286.737,51.28 286.737,52.41 ; 288.199,52.591 288.434,52.356 v1(288.434,51.766) ; v1(288.719,21.249) 288.719,21.289 288.791,21.361 C371.2@288.791,22.185 ; v1@130.227,85.222 131.922,85.222 132.05,85.35 v1(132.09,85.35) ; v1@130.227,85.222 130.172,85.222 v1(130.157,85.207) 130.212,85.207 v1@130.227,85.222 ; 132.151,83.135 133.25,83.135 133.635,83.521 U15.N4@133.65,83.521 ; 143.209,78.34 143.429,78.56 U3.W3@143.429,78.578 U3.V3@143.429,79.228 143.447,79.228 143.505,79.17 U3.V5@144.654,79.17 ; 143.209,78.34 143.209,78.166 U3.Y3@143.429,77.946 ; U3.V5@144.654,79.17 144.874,78.95 144.99,78.95 145.361,78.578 U3.W6@145.379,78.578 ; U3.Y5@144.729,77.928 U3.Y6@145.379,77.928 145.379,77.946 145.682,78.248 145.682,78.258 ; U3.W6@145.379,78.578 145.379,78.56 145.682,78.258 ; U3.AJ9@147.311,72.078 U3.AJ9@147.329,72.078 U3.AK10@147.979,71.428 U3.AK11@148.629,71.428 ; v1(147.678,85.37) 147.7,85.392 v1@147.7,85.431 ; v1(147.678,85.37) 147.678,85.408 v1@147.7,85.431 ; v1(147.678,85.37) 147.683,85.37 147.974,85.078 U3.J10@147.979,85.078 U3.J11@148.629,85.078 ; U3.E18@153.179,87.696 153.033,87.842 153.033,88.814 153.179,88.96 U3.C18@153.179,88.978 ; v1@156.088,87.998 156.418,88.328 U3.D23@156.429,88.328 ; U3.AA23@156.429,77.296 U3.Y23@156.429,77.928 U3.W23@156.429,78.578 U3.V23@156.429,79.228 156.429,79.704 156.443,79.717 156.429,79.73 U3.U23@156.429,79.878 U3.T23@156.429,80.528 U3.T24@157.079,80.528 U3.T25@157.729,80.528 U3.T26@158.379,80.528 158.397,80.528 158.657,80.788 v1(158.688,80.788) 158.716,80.76 158.779,80.76 159.011,80.528 U3.T27@159.029,80.528 ; U3.J28@159.679,85.078 U3.H28@159.679,85.728 ; v1@273.488,69.987 273.781,69.695 U1.H16@273.781,69.68 273.802,69.68 274.13,69.351 v1(274.201,69.351) 274.18,69.373 274.18,69.955 U1.G15@274.653,70.428
  Top Layer 1 _Signal w0.381: v1(9.889,104.862) 12.286,104.862 U41.9@12.889,105.466 ; U41.4@14.794,101.666 14.794,100.35 v1(14.927,100.218) ; v1(17.93,100.152) 17.935,100.152 18.032,100.055 U63.4@19.898,100.055 ; U15.AB5@132.85,89.371 133.156,89.677 v1(133.156,89.803) ; v1(134.117,90.687) 134.117,90.196 134.45,89.862 U15.AB3@134.45,89.371 ; U15.G1@136.05,79.621 136.235,79.806 137.701,79.806 139.492,81.597 ; v1(138.502,17.888) 138.514,17.9 U13.1@138.514,19.231 ; 139.653,81.758 141.95,81.758 142.021,81.828 U3.P1@142.129,81.828 ; U14.1@141.165,19.222 141.165,17.876 v1(141.178,17.862) ; v1(142.922,17.143) 142.925,17.14 142.925,14.699 J6.4@142.927,14.697 ; 150.455,100.438 150.455,100.975 150.474,100.994 ; v1(150.477,105.986) 150.874,105.589 U12.N11@150.904,105.589 151.299,105.983 151.299,106.16 151.528,106.389 U12.P12@151.554,106.389 ; 150.494,100.975 150.474,100.994 ; v1(151.935,102.191) 151.909,102.191 151.33,101.612 151.092,101.612 150.474,100.994 ; v1(152.83,100.898) 152.854,100.873 U12.T5@152.854,100.789 ; U12.T12@152.854,106.389 152.854,106.245 v1(153.132,105.967) ; v1(153.183,103.516) 153.183,103.503 152.869,103.189 U12.T8@152.854,103.189 152.854,103.143 152.552,102.841 152.552,102.257 152.78,102.029 v1(152.78,102.024) 153.768,102.024 153.952,101.839 v1(153.957,101.839) 153.957,100.986 U12.V5@154.154,100.789 ; 153.892,106.051 153.892,106.127 U12.V12@154.154,106.389 U12.V12@154.169,106.389 ; v1(154.15,102.835) 154.116,102.869 154.116,103.151 U12.V8@154.154,103.189 ; U12.W9@154.804,103.989 155.454,103.339 U12.Y8@155.454,103.189 155.454,102.542 v1(155.972,102.024) 155.969,102.02 155.677,102.02 155.287,101.63 155.287,100.957 U12.Y5@155.454,100.789 ; U12.W11@154.804,105.589 155.13,105.914 155.13,106.064 U12.Y12@155.454,106.389 155.454,107.067 C368.2@156.461,108.074 156.721,107.815 157.34,107.815 157.493,107.662 v1(157.498,107.662) 157.503,107.662 157.933,107.233 C322.2@158.155,107.233 ; v1@155.972,102.019 156.515,101.476 156.515,101.028 U12.AB5@156.754,100.789 156.754,102.169 156.958,102.373 156.958,102.985 U12.AB8@156.754,103.189 ; U12.AB3@156.754,99.189 157.106,99.54 v1(159.549,99.54) ; U12.AB10@156.754,104.789 v1(158.541,106.576) ; C366.2@158.106,103.324 158.176,103.394 159.908,103.394 v1(159.912,103.398) ; v1(159.483,102.296) 159.483,102.291 159.491,102.283 C338.2@159.491,101.306 ; J7.7@161.941,17.487 161.941,14.527 v1(162.044,14.424) ; J7.4@165.691,17.262 165.691,14.34 165.716,14.315 v1(165.716,14.31) ; v1(171.933,4.968) 171.938,4.968 172.069,4.837 C501.1@178.276,4.837 ; v1(178.882,7.695) 178.885,7.699 179.653,7.699 179.662,7.708 179.901,7.708 U23.C2@179.896,7.714 ; 179.881,7.93 179.881,7.742 U23.C2@179.853,7.714 U23.C2@179.896,7.714 ; U23.B3@180.253,8.114 180.419,8.112 180.431,8.124 180.552,8.124 180.653,8.023 U23.C4@180.653,7.714 U23.C3@180.253,7.714 U23.C2@179.896,7.714 ; v1(180.626,40.331) 180.675,40.331 180.874,40.53 C509.1@181.831,40.53 181.835,40.533 181.835,42.224 C510.1@181.838,42.227 ; v1(221.547,100.757) 222.22,100.757 R270.1@222.244,100.734 ; v1(222.534,106.404) 222.534,106.395 223.035,105.894 R271.1@223.035,105.053 ; U53.3@225.476,104.728 225.476,105.157 v1(225.56,105.242) ; C675.2@228.163,98.482 230.513,98.482 v1(230.554,98.522) ; C676.2@228.224,100.736 229.273,100.736 229.302,100.765 v1(229.308,100.765) ; R230.1@228.856,86.236 228.856,87.154 v1(229.208,87.506) ; C677.2@229.1,103.059 229.115,103.045 v1(230.676,103.045) ; C349.2@229.841,82.785 231.141,82.785 231.565,82.361 231.565,82.233 v1(231.568,82.229) ; U49.49@231.241,55.205 233.15,57.114 233.311,57.114 233.404,57.208 233.695,57.208 v1(233.699,57.211) 233.702,57.208 233.702,56.525 233.715,56.513 v1(233.715,56.508) 233.716,56.506 233.716,55.642 v1(233.718,55.64) ; v1(232.101,82.074) 232.107,82.08 232.107,83.192 ; C540.1@233.237,94.05 233.513,94.326 v1(233.513,95.4) ; U39.11@233.689,83.684 233.689,82.455 233.716,82.428 v1(233.716,82.423) ; U47.49@235.638,36.085 235.638,36.412 U47.49@235.7,36.474 ; v1(237.827,70.174) 237.945,70.292 U52.11@240.045,70.292 ; C664.1@239.732,56.698 241.161,56.698 241.211,56.748 v1(241.216,56.748) ; C668.2@242.142,99.891 243.314,99.891 v1(243.321,99.898) ; C667.2@242.149,97.621 242.238,97.532 242.238,96.093 ; C669.2@242.666,102.377 243.728,102.377 243.779,102.429 v1(243.784,102.429) ; v1(260.432,47.702) 260.582,47.702 260.904,47.379 U50.J13@260.919,47.379 ; U50.H16@261.919,44.379 U50.H16@261.919,44.394 ; v1(262.331,44.872) 262.331,44.806 U50.H16@261.919,44.394 ; U50.F13@263.919,47.379 U50.E14@264.919,46.379 U50.F15@263.919,45.379 U50.G15@262.919,45.379 U50.H15@261.919,45.379 U50.H16@261.919,44.394 ; C185.1@284.186,49.892 286.235,49.892 286.552,50.209 v1(286.557,50.209) ; R388.1@286.572,36.136 287.162,36.136 v1(287.168,36.142) ; R390.1@286.937,37.94 286.969,37.907 v1(287.562,37.907)
  Top Layer 1 _Signal w0.508: v1(153.091,63.093) 153.136,63.137 153.136,63.833 C274.2@153.257,63.954 ; v1(153.214,60.707) 153.381,60.875 C273.2@153.381,61.814 ; C38.2@153.339,65.947 153.339,66.022 153.943,66.625 v1(154.26,66.625) ; C245.2@156.307,65.941 156.186,65.82 156.186,65.301 v1(156.034,65.149) 156.294,64.888 156.294,64.239 C246.2@156.415,64.118 ; USB1.6@199.008,129.403 199.382,129.778 v1(200.943,129.778) ; USB1.9@199.008,134.903 201.174,134.903 v1(201.258,134.987) ; USB1.5@201.858,129.303 201.858,131.215 202.885,132.243 v1(202.885,133.221) ; v1(207.879,126.978) 207.908,127.006 USB1.7@207.908,129.403 USB1.8@207.908,134.903 207.965,134.846 210.165,134.846 v1(210.213,134.799) ; C682.2@227.218,115.415 227.218,116.551 v1(227.379,116.713) ; v1(229.105,116.713) 229.22,116.598 C681.2@229.22,115.401 ; v1(231.389,116.857) 231.473,116.773 C679.2@231.473,115.409 ; 233.492,117.594 233.724,117.363 C680.2@233.724,115.408 ; v1(241.043,117.163) 241.043,116.061 C674.2@241.12,115.985 ; v1(242.931,117.109) 242.931,116.212 C671.2@243.096,116.048 ; C673.2@245.366,116.043 245.506,116.043 245.78,116.316 245.78,117.332 v1(246.042,117.594) ; C625.1@247.481,81.448 249.079,81.448 249.093,81.434 v1(249.125,81.434) ; C624.1@247.502,79.491 249.055,79.491 v1(249.256,79.692) ; C623.1@247.541,77.52 247.711,77.69 v1(249.207,77.69) ; C622.1@247.543,75.55 247.634,75.459 v1(249.158,75.459) ; C621.1@247.578,73.506 249.077,73.506 v1(249.142,73.571) ; C620.1@247.582,71.54 249.048,71.54 v1(249.077,71.568) ; C672.2@247.635,116.026 247.668,116.059 v1(247.668,117.561) ; v1(251.77,117.3) 253.262,117.3 C533.1@253.483,117.521 ; v1(251.999,119.167) 253.24,119.167 253.461,119.388 C534.1@253.461,119.568 ; J3.3@252.821,72.048 J3.5@254.091,72.048 254.091,71.352 254.208,71.235 255.287,71.235 255.507,71.015 v1(255.67,71.015) ; C533.1@253.262,117.257 253.483,117.478 C533.1@253.483,117.521 ; C533.1@253.483,117.619 C533.1@253.483,117.521 ; v1(253.887,111.69) 253.956,111.76 C536.1@253.956,113.194 ; C486.2@254.522,91.024 254.632,90.913 254.632,89.652 ; v1(255.934,112.079) 255.985,112.13 C535.1@255.985,113.18 ; J1.10@259.156,93.732 259.209,93.786 259.209,94.734 v1(259.291,94.816) ; v1(260.348,90.403) 260.426,90.48 J1.2@260.426,92.462 ; v1(260.44,65.072) 261.692,66.324 261.692,69.144 261.925,69.377 261.925,69.826 261.609,70.142 R42.2@261.609,70.391 ; U2.4@262.662,103.772 262.662,105.775 v1(262.809,105.923) ; C537.2@264.444,120.859 264.444,122.076 v1(264.534,122.167) ; v1(265.371,109.288) 265.371,109.33 265.428,109.387 265.428,110.483 265.444,110.499 R163.1@265.444,111.968 ; U48.9@267.456,114.652 268.837,114.652 v1(268.909,114.724) ; C528.2@269.353,106.656 271.153,106.656 v1(271.21,106.714) ; C529.1@270.663,109.048 272.739,109.048 v1(272.822,109.131) ; C530.1@270.663,112.089 272.481,112.089 v1(272.75,111.821)
  Top Layer 1 _Signal w0.635: U50.D11@265.919,49.294 U50.D11@265.919,49.379
  Bottom Layer_Signals w0.132: C421.2@127.991,74.743 128.025,74.777 128.558,74.777 v1(128.592,74.811) ; v1(132.09,85.35) 132.093,85.353 132.661,85.353 C409.2@132.664,85.356 ; v1(178.954,78.746) 179.005,78.798 179.114,78.798 179.131,78.815 179.271,78.675 v1(180.267,78.675)
  Bottom Layer_Signals w0.152: v1(149.577,71.716) 149.577,71.651 149.941,71.287 C459.1@149.987,71.287 ; v1(161.364,79.584) 161.76,79.979 161.76,80.195 161.815,80.25 C23.2@161.861,80.25 ; v1(279.194,99) 279.261,99 279.351,98.91 279.406,98.91 279.615,98.701 ; C7.1@279.637,98.048 279.615,98.07 279.615,98.701 ; C9.1@279.706,100.219 279.706,100.209 279.706,99.553 279.601,99.447 279.601,99.07 C8.1@279.62,99.051 279.615,99.046 279.615,98.701 ; C10.1@282.191,98.561 282.968,98.561 283.18,98.773 v1(283.247,98.773)
  Bottom Layer_Signals w0.178: C407.2@132.189,86.187 132.189,86.197 132.504,86.513 132.504,86.625 v1(132.546,86.667)
  Bottom Layer_Signals w0.2: C334.2@142.128,98.705 142.118,98.705 140.586,97.172 140.129,97.172 139.47,96.513 v1(139.47,95.877) 142.291,95.877 142.522,96.108 142.532,96.108 142.572,96.148 C346.2@142.572,96.158 142.572,96.607 142.583,96.618 142.583,96.996 C356.2@142.623,97.036 ; C359.2@142.153,101.654 C359.2@142.153,101.654 142.204,101.652 142.244,101.612 142.244,101.532 142.291,101.485 142.291,101.173 142.311,101.154 142.311,100.584 C344.2@142.295,100.568 ; C359.2@142.193,101.654 142.193,101.704 142.359,101.87 142.359,101.896 142.642,102.179 v7(142.642,102.233) ; C344.2@142.295,100.558 142.477,100.377 142.477,100.367 142.609,100.234 143.17,100.234 143.604,100.668 143.604,101.172 C392.2@143.681,101.249 ; C365.2@142.33,102.653 142.345,102.637 142.345,102.203 142.446,102.103 142.446,102.033 ; v1(143.195,68.308) 143.229,68.342 R99.1@143.229,68.948 ; C339.2@143.488,109.027 143.834,108.681 143.834,107.686 144.015,107.505 v1(144.015,107.451) ; v1(144.434,107.065) 144.441,107.072 144.441,107.671 C363.2@144.449,107.678 ; C327.2@146.204,101.324 146.244,101.364 146.244,101.567 146.321,101.644 v1(146.321,101.698) ; v1(146.349,69.182) 147.455,70.289 147.455,70.735 147.542,70.821 147.542,71.094 C454.2@147.573,71.125 147.594,71.146 148.005,71.146 148.182,71.324 148.639,71.324 148.649,71.313 C473.2@148.67,71.313 ; C337.2@147.049,107.062 147.089,107.102 147.089,107.112 147.255,107.279 147.255,107.304 147.567,107.616 147.567,107.791 ; C324.2@147.17,96.876 147.18,96.876 147.403,97.099 147.537,97.099 v1(147.576,97.137) ; C323.2@147.607,108.066 147.607,107.791 148.033,107.791 v1(148.453,108.211) 148.903,107.762 C336.2@148.903,107.138 ; v1(147.924,102.587) 147.962,102.625 147.962,102.825 148.114,102.977 148.114,102.987 C318.2@148.154,103.027 ; v1(152.356,95.246) 152.356,95.3 152.285,95.371 152.285,95.755 152.354,95.824 152.354,96.215 C317.2@152.394,96.255 ; v1(152.83,100.898) 152.868,100.859 152.988,100.859 153.244,100.604 C361.2@153.254,100.604 ; v1(153.957,101.839) 154.256,101.541 154.256,101.447 C335.2@154.296,101.407 ; C360.2@158.886,97.507 158.91,97.483 159.449,97.483 v1(159.473,97.46) ; v1(161.372,84.113) 161.426,84.113 161.71,84.397 162.787,84.397 162.97,84.214 162.97,84.109 163.001,84.077 C30.2@163.047,84.077
  Bottom Layer_Signals w0.203: C398.2@123.965,85.584 123.981,85.6 124.919,85.6 124.921,85.602 C397.2@124.967,85.602 125.554,85.602 125.658,85.706 v1(125.711,85.706) ; v1(125.147,86.999) 125.149,86.997 125.546,86.997 C429.2@125.549,86.995 ; v1@125.711,85.617 126.03,85.617 C399.2@126.034,85.621 ; C433.2@125.885,89.282 126.044,89.123 126.273,89.123 126.422,88.974 v1(126.475,88.974) ; v1(131.711,88.466) 131.719,88.458 131.719,87.789 C425.2@131.748,87.76 ; C364.2@142.017,105.755 142.017,105.798 142.011,105.803 142.011,106.704 C362.2@142.042,106.734 ; C472.1@144.534,75.391 144.514,75.41 144.514,75.861 144.795,76.142 144.795,76.445 145.12,76.77 v1(145.12,76.824) ; v1(154.009,70.021) 154.559,70.57 154.559,71.509 R98.1@154.595,71.545 154.559,71.582 154.559,72.237 154.848,72.527 C267.2@154.924,72.527
  Bottom Layer_Signals w0.229: C120.2@263.461,65.727 263.485,65.703 263.485,64.921 263.775,64.631 263.822,64.584 264.331,64.584 264.521,64.775 C115.2@264.521,64.785 ; v1(270.961,74.78) 270.961,74.826 271.042,74.907 C124.2@271.042,75.564 ; v1(271.739,73.272) 271.771,73.305 271.86,73.305 272.256,73.701 C126.2@272.256,73.711 C125.2@272.256,74.761 ; C137.2@273.64,75.777 273.64,75.767 273.665,75.741 273.99,75.741 274.008,75.722 274.324,75.722 274.809,76.208 275.232,76.208 275.581,76.557 276.004,76.557 276.211,76.35 276.211,76.32 276.353,76.179 C128.2@276.353,76.169 276.378,76.194 276.378,76.409 276.556,76.586 v1(276.556,76.633) ; C130.2@274.411,74.089 274.411,74.705 274.501,74.794 274.511,74.794 C141.2@274.576,74.729 274.602,74.755 274.98,74.755 275.044,74.819 275.118,74.744 C146.2@275.651,74.744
